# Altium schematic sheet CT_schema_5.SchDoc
size 283 x 147 mm
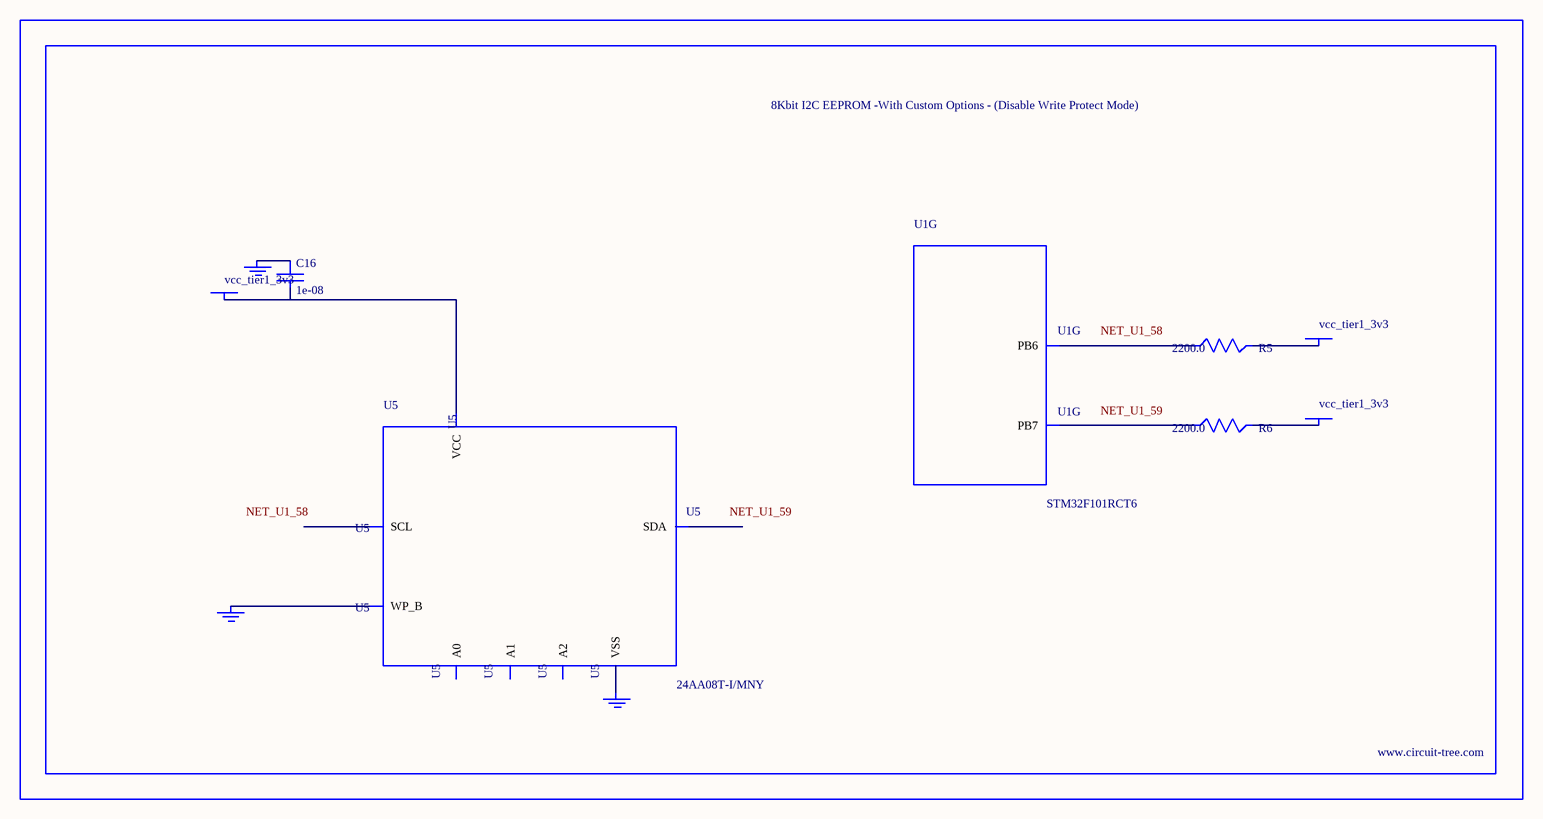
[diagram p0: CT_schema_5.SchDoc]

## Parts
BORDER4  (no value)
C16  1e-08  [C0402]
GND_INSTANCE_4_0  (no value)
GND_INSTANCE_4_1  (no value)
GND_INSTANCE_4_2  (no value)
POWER_INSTANCE_4_0  vcc_tier1_3v3
POWER_INSTANCE_4_1  vcc_tier1_3v3
POWER_INSTANCE_4_2  vcc_tier1_3v3
R5  2200.0  [R0603]
R6  2200.0  [R0603]
U1  STM32F101RCT6  [LQFP64]  (part G of 7)
U5  24AA08T-I/MNY  [TDFN-8/6MM]

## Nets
NetC16_1: C16.1 GND_INSTANCE_4_1.0(GND)
NetC16_2: C16.2 POWER_INSTANCE_4_0.0(PWR) U5.8(VCC)
NetGND_INSTANCE_4_0_0: GND_INSTANCE_4_0.0(GND) U5.7(WP_B)
NetGND_INSTANCE_4_2_0: GND_INSTANCE_4_2.0(GND) U5.4(VSS)
NetPOWER_INSTANCE_4_1_0: POWER_INSTANCE_4_1.0(PWR) R5.2
NetPOWER_INSTANCE_4_2_0: POWER_INSTANCE_4_2.0(PWR) R6.2
NetR5_1: R5.1 U1.58(PB6)
NetR6_1: R6.1 U1.59(PB7)

Not connected (* = marked no-connect by the designer): U5 1(A0) 2(A1) 3(A2) 5(SDA) 6(SCL)

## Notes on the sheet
- Labels drawn without touching a wire or pin: NET_U1_58, NET_U1_59

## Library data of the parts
BORDER4 = BORDER_PAGE4
C16 = C0402C103K3RAC
GND_INSTANCE_4_0-GND_INSTANCE_4_2 = GND
POWER_INSTANCE_4_0-POWER_INSTANCE_4_2 = PWR
R5 R6 = RC0603JR-072K2L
